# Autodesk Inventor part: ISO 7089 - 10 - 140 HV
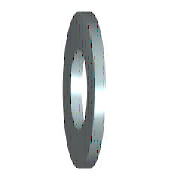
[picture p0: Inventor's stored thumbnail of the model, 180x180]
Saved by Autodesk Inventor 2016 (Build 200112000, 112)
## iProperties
IsCustomPart: 0
Created: 2013-09
Part Number: ISO 7089 - 10 - 140 HV
Material: Stainless Steel, 440C
Description: FLAT WASHER SST
Document SubType Name: Modeling
Standard: ISO 7089
Designer: normanpa
Standard Revision: Second edition 2000-06-01
Standards Organization: ISO
Language: en-US
Size Designation: 10 - 140 HV
Categories: <MemberInstance><Categories><Category DisplayName="Fasteners" InternalName="e4da775c-781d-43d5-af7c-5136215cf5a6" Mnemonic="FSTN"><Category DisplayName="Washers
Density: 7.75 g/cm^3
Appearance: Semi-Polished
Mass: 3.52732 g
Surface Area: 6.46775 cm^2
Volume: 0.455138 cm^3
Author: normanpa
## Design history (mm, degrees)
sketch "Sketch"
  geometry: C1 r 10 at (0, 0); C2 r 5.25 at (0, 0); 1 further point
  constraints: 2 centre point, 2 coincident
  dimensions: "d0" = 10.5 diameter of C2 (= SD1); "d1" = 20 diameter of C1 (= SD2)
extrude "Body" new body sketch "Sketch" distance "d2" = 2 (= SD); taper "d3" = 0 deg
workaxis "Work Axis1"
workplane "Work Plane1"
body "Solid1"
other parameters: "SD1" = 10.5 [user parameter; used in 1 equation term], "SD2" = 20 [user parameter; used in 1 equation term], "SD" = 2 [user parameter; used in 1 equation term], "d4" = 0, "d5" = 0, "d6" = 0, "d7" = 0
